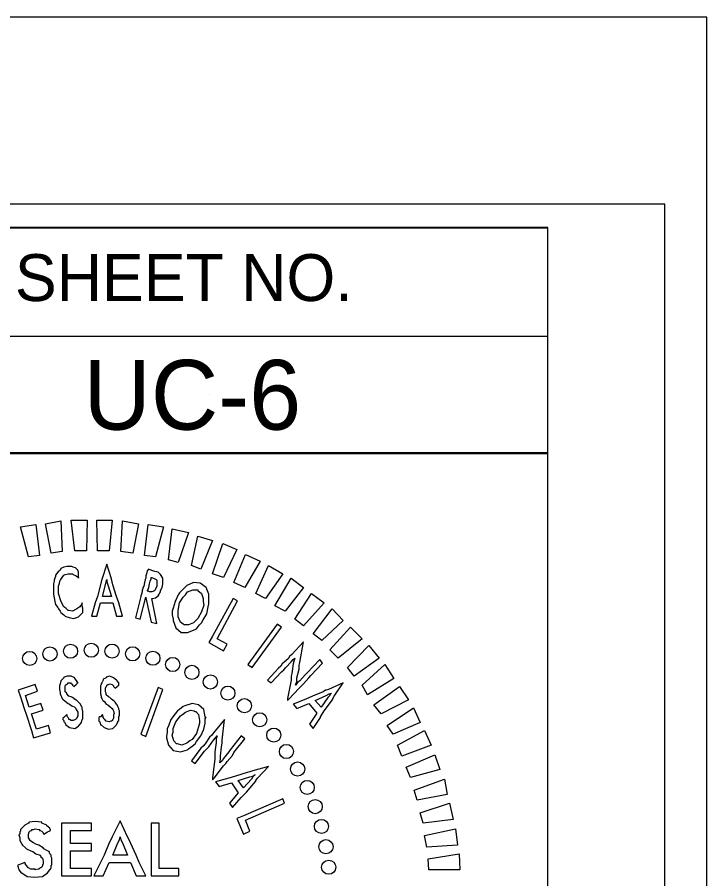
# Model space of a CAD drawing. Extents: x 0 to 7954, y -383 to 1504.
# Drawn here: x 2.7104 to 2.8333, y 1.6798 to 1.8333 of the extents above; entities that cross this region are included whole.
import ezdxf

# ---------------------------------------------------------------- set-up
doc = ezdxf.new("R2010")
doc.units = 0
for name, color, linetype in [('Concrete Pattern CELL', 7, 'Continuous'), ('UC Plan Profile Sheet 34 CELL', 7, 'Continuous'), ('UC Plan Sheet 34 CELL', 7, 'Continuous')]:
    doc.layers.add(name, color=color, linetype=linetype)

msp = doc.modelspace()

# ---------------------------------------------------------------- linework, layer by layer
at = {"layer": 'Concrete Pattern CELL'}
for points in [[(2.71245, 1.73716), (2.71101, 1.74252), (2.71376, 1.74291), (2.71441, 1.73742)], [(2.7165, 1.73781), (2.71545, 1.74304), (2.7182, 1.74357), (2.71846, 1.73808)], [(2.72068, 1.73821), (2.72003, 1.7437), (2.7229, 1.7437), (2.72277, 1.73821)], [(2.72473, 1.73821), (2.7246, 1.7437), (2.72735, 1.7437), (2.72683, 1.73821)], [(2.72892, 1.73808), (2.72918, 1.74357), (2.73205, 1.74304), (2.73101, 1.73781)], [(2.7331, 1.73742), (2.73375, 1.74291), (2.7365, 1.74252), (2.73506, 1.73716)], [(2.73741, 1.73664), (2.73807, 1.74213), (2.74094, 1.74147), (2.73911, 1.73612)], [(2.74147, 1.73559), (2.74264, 1.74082), (2.74526, 1.74004), (2.74317, 1.73494)], [(2.74526, 1.73415), (2.74709, 1.73951), (2.74957, 1.73847), (2.74722, 1.7335)], [(2.74905, 1.73259), (2.75114, 1.73755), (2.75375, 1.73638), (2.75101, 1.73167)], [(2.75297, 1.73063), (2.75519, 1.73559), (2.7578, 1.73415), (2.75467, 1.72971)], [(2.75637, 1.7284), (2.75924, 1.73337), (2.76146, 1.73167), (2.7582, 1.72749)], [(2.7599, 1.72605), (2.7629, 1.73063), (2.76512, 1.72893), (2.76146, 1.72487)], [(2.76316, 1.72344), (2.76656, 1.72788), (2.76852, 1.72579), (2.76473, 1.72226)], [(2.75676, 1.72514), (2.75153, 1.71795), (2.75231, 1.71742), (2.75754, 1.72461)], [(2.76617, 1.72056), (2.76983, 1.72461), (2.77192, 1.72252), (2.76761, 1.71912)], [(2.76931, 1.71742), (2.7731, 1.72135), (2.77493, 1.71912), (2.77048, 1.71586)], [(2.77192, 1.71429), (2.77597, 1.71795), (2.77754, 1.71546), (2.77284, 1.71259)], [(2.73558, 1.71389), (2.73245, 1.70553), (2.73336, 1.70514), (2.73637, 1.7135)], [(2.77401, 1.71076), (2.77859, 1.71403), (2.78016, 1.71167), (2.77532, 1.70919)], [(2.77637, 1.7071), (2.78107, 1.71023), (2.78225, 1.70762), (2.77741, 1.70553)], [(2.7782, 1.70357), (2.78303, 1.70618), (2.78421, 1.70357), (2.77898, 1.70161)], [(2.77976, 1.69965), (2.78486, 1.70187), (2.78578, 1.69926), (2.78055, 1.69782)], [(2.7812, 1.6956), (2.78656, 1.69756), (2.78708, 1.69481), (2.78172, 1.69377)], [(2.78225, 1.69154), (2.78748, 1.69324), (2.78813, 1.69037), (2.78277, 1.68971)], [(2.78303, 1.68749), (2.78852, 1.68867), (2.78891, 1.68579), (2.78342, 1.6854)], [(2.78369, 1.68331), (2.78918, 1.68422), (2.78931, 1.68135), (2.78382, 1.68135)]]:
    msp.add_lwpolyline(points, close=True, dxfattribs=at)
for points in [[(2.72134, 1.73442), (2.72121, 1.73481), (2.72081, 1.7352), (2.72042, 1.73533), (2.72016, 1.73546), (2.71925, 1.73546), (2.71872, 1.73533), (2.7182, 1.73507), (2.71807, 1.73481), (2.71768, 1.73442), (2.71728, 1.73389), (2.71728, 1.73376), (2.71728, 1.73363), (2.71715, 1.73337), (2.71702, 1.73298), (2.71702, 1.73285), (2.71689, 1.73232), (2.71689, 1.7318), (2.71689, 1.73049), (2.71715, 1.72919), (2.71728, 1.72866), (2.71768, 1.72814), (2.71781, 1.72788), (2.71807, 1.72749), (2.7182, 1.72723), (2.71872, 1.72683), (2.71898, 1.72657), (2.71925, 1.72644), (2.7199, 1.72631), (2.72055, 1.72618), (2.72134, 1.72644), (2.7216, 1.7267), (2.72186, 1.72697), (2.72212, 1.72723), (2.72212, 1.72775), (2.72212, 1.72801), (2.72199, 1.7284), (2.72199, 1.72866), (2.72199, 1.72893), (2.72186, 1.72866), (2.7216, 1.72827), (2.72108, 1.72788), (2.72029, 1.72749), (2.71964, 1.72762), (2.71951, 1.72762), (2.71911, 1.72801), (2.71872, 1.72827), (2.71846, 1.7288), (2.7182, 1.72932), (2.71781, 1.73063), (2.71781, 1.73193), (2.71794, 1.73246), (2.71807, 1.73298), (2.7182, 1.73311), (2.71846, 1.7335), (2.71872, 1.73389), (2.71898, 1.73402), (2.71951, 1.73415), (2.72029, 1.73415), (2.72042, 1.73402), (2.72094, 1.73376), (2.72134, 1.7335), (2.72134, 1.73337), (2.72134, 1.7335), (2.72134, 1.73389), (2.72134, 1.73415), (2.72134, 1.73429), (2.72134, 1.73442), (2.72134, 1.73442)], [(2.72722, 1.73311), (2.72722, 1.73324), (2.72643, 1.73585), (2.72552, 1.73311), (2.72539, 1.73272), (2.72526, 1.73219), (2.72473, 1.7301), (2.72434, 1.72893), (2.72369, 1.72657), (2.7246, 1.72657), (2.72526, 1.72893), (2.72748, 1.72893), (2.72813, 1.72657), (2.72918, 1.72657), (2.72853, 1.72893), (2.72813, 1.7301), (2.72748, 1.73219), (2.72735, 1.73272), (2.72722, 1.73311), (2.72722, 1.73311)], [(2.73637, 1.73298), (2.73637, 1.73337), (2.73598, 1.73402), (2.73558, 1.73442), (2.73493, 1.73455), (2.73375, 1.73494), (2.73375, 1.73481), (2.73362, 1.73468), (2.73349, 1.73415), (2.73336, 1.73376), (2.73336, 1.73363), (2.73336, 1.7335), (2.73336, 1.73337), (2.73323, 1.73311), (2.7331, 1.73259), (2.73297, 1.73193), (2.73284, 1.73167), (2.73284, 1.73141), (2.73271, 1.73128), (2.73271, 1.73089), (2.73258, 1.73049), (2.73245, 1.73023), (2.73245, 1.7301), (2.73153, 1.72631), (2.73232, 1.72605), (2.73336, 1.72997), (2.73336, 1.72984), (2.73428, 1.72553), (2.73532, 1.72527), (2.73441, 1.72971), (2.73454, 1.72971), (2.73506, 1.72984), (2.73558, 1.73023), (2.73571, 1.73049), (2.73585, 1.73076), (2.73598, 1.73089), (2.73598, 1.73115), (2.73624, 1.73167), (2.73637, 1.73232), (2.73637, 1.73259), (2.73637, 1.73272), (2.73637, 1.73298)], [(2.72643, 1.73311), (2.72643, 1.73272), (2.72656, 1.73219), (2.72722, 1.7301), (2.72565, 1.7301), (2.72617, 1.73219), (2.7263, 1.73272), (2.72643, 1.73311), (2.72643, 1.73311)], [(2.73441, 1.7335), (2.73493, 1.73324), (2.73519, 1.73311), (2.73532, 1.73298), (2.73532, 1.73259), (2.73532, 1.73193), (2.73506, 1.73141), (2.73493, 1.73115), (2.7348, 1.73102), (2.73441, 1.73089), (2.73402, 1.73089), (2.73375, 1.73102), (2.73362, 1.73102), (2.73375, 1.73128), (2.73375, 1.73141), (2.73388, 1.73167), (2.73402, 1.73232), (2.73415, 1.73285), (2.73428, 1.73324), (2.73428, 1.73337), (2.73428, 1.7335), (2.73441, 1.7335), (2.73441, 1.7335)], [(2.74186, 1.73259), (2.74068, 1.73206), (2.74055, 1.73193), (2.74042, 1.7318), (2.7399, 1.73128), (2.73937, 1.73076), (2.73911, 1.73036), (2.73859, 1.72919), (2.7382, 1.72801), (2.73807, 1.72749), (2.73807, 1.72683), (2.7382, 1.72605), (2.7382, 1.72579), (2.73872, 1.72448), (2.73964, 1.7237), (2.74081, 1.7237), (2.74212, 1.72422), (2.74238, 1.72435), (2.7429, 1.72501), (2.7433, 1.7254), (2.74356, 1.72592), (2.74421, 1.72697), (2.74447, 1.72827), (2.7446, 1.7288), (2.7446, 1.72932), (2.7446, 1.7301), (2.7446, 1.73036), (2.7446, 1.73049), (2.74408, 1.73167), (2.74303, 1.73246), (2.74186, 1.73259), (2.74186, 1.73259)], [(2.74264, 1.73128), (2.74264, 1.73115), (2.7433, 1.73063), (2.74356, 1.72971), (2.74356, 1.72919), (2.74369, 1.72853), (2.7433, 1.72736), (2.74264, 1.72618), (2.74225, 1.72579), (2.74186, 1.7254), (2.74094, 1.72501), (2.74029, 1.72501), (2.74016, 1.72501), (2.74003, 1.72514), (2.73951, 1.72553), (2.73911, 1.72644), (2.73911, 1.7271), (2.73911, 1.72762), (2.73937, 1.72893), (2.74003, 1.72997), (2.74042, 1.73036), (2.74081, 1.73089), (2.74173, 1.73128), (2.74251, 1.73128), (2.74264, 1.73128), (2.74264, 1.73128)], [(2.74526, 1.72304), (2.7446, 1.72187), (2.74722, 1.72043), (2.74787, 1.72161), (2.74604, 1.72252), (2.7497, 1.72932), (2.74892, 1.72971), (2.74526, 1.72304), (2.74526, 1.72304)], [(2.76003, 1.71429), (2.76029, 1.71494), (2.76029, 1.71559), (2.76068, 1.71716), (2.76068, 1.71782), (2.76081, 1.71834), (2.76146, 1.722), (2.75937, 1.71978), (2.75898, 1.71938), (2.75872, 1.71899), (2.75767, 1.71808), (2.75741, 1.71769), (2.75702, 1.71729), (2.75506, 1.7152), (2.75571, 1.71468), (2.75754, 1.71664), (2.75794, 1.71703), (2.75833, 1.71742), (2.75924, 1.71847), (2.75963, 1.71886), (2.7599, 1.71912), (2.75977, 1.71873), (2.75963, 1.71808), (2.75937, 1.71638), (2.75924, 1.71586), (2.75924, 1.7152), (2.75859, 1.71193), (2.75859, 1.71154), (2.75885, 1.7118), (2.76068, 1.71376), (2.76107, 1.71416), (2.76146, 1.71455), (2.76238, 1.71559), (2.76277, 1.71599), (2.76486, 1.71821), (2.76434, 1.71886), (2.76212, 1.71651), (2.76173, 1.71612), (2.76081, 1.71507), (2.76042, 1.71481), (2.76003, 1.71429), (2.76003, 1.71429)], [(2.71872, 1.71559), (2.71833, 1.7152), (2.7182, 1.71507), (2.71807, 1.71455), (2.71807, 1.71442), (2.71794, 1.71429), (2.71794, 1.71416), (2.71794, 1.71403), (2.71794, 1.71389), (2.71794, 1.71363), (2.71794, 1.7135), (2.71807, 1.71298), (2.71807, 1.71272), (2.7182, 1.71246), (2.71833, 1.7122), (2.71846, 1.71193), (2.71859, 1.7118), (2.71898, 1.71141), (2.71951, 1.71102), (2.71977, 1.71089), (2.72016, 1.71063), (2.72068, 1.71037), (2.72081, 1.71023), (2.72094, 1.70997), (2.72121, 1.70945), (2.72121, 1.70932), (2.72121, 1.70893), (2.72121, 1.7088), (2.72108, 1.70854), (2.72108, 1.7084), (2.72094, 1.70827), (2.72081, 1.70814), (2.72042, 1.70801), (2.72003, 1.70801), (2.71977, 1.70814), (2.71964, 1.70814), (2.71964, 1.70827), (2.71951, 1.70854), (2.71938, 1.70867), (2.71925, 1.70906), (2.71885, 1.70867), (2.71872, 1.70854), (2.71859, 1.7084), (2.71859, 1.70814), (2.71872, 1.70801), (2.71872, 1.70788), (2.71872, 1.70775), (2.71885, 1.70775), (2.71911, 1.70723), (2.71977, 1.70671), (2.72068, 1.70657), (2.72134, 1.70697), (2.72186, 1.70762), (2.72199, 1.70814), (2.72212, 1.70827), (2.72212, 1.70854), (2.72212, 1.70867), (2.72212, 1.70893), (2.72212, 1.70906), (2.72212, 1.70945), (2.72212, 1.70958), (2.72199, 1.7101), (2.72199, 1.71037), (2.72186, 1.7105), (2.72173, 1.71089), (2.72147, 1.71115), (2.72134, 1.71128), (2.72094, 1.71167), (2.72081, 1.71167), (2.72029, 1.71206), (2.72003, 1.7122), (2.71964, 1.71233), (2.71925, 1.71272), (2.71925, 1.71285), (2.71898, 1.71311), (2.71898, 1.71363), (2.71898, 1.71376), (2.71898, 1.71416), (2.71911, 1.71442), (2.71925, 1.71442), (2.71938, 1.71455), (2.71951, 1.71468), (2.7199, 1.71468), (2.72003, 1.71455), (2.72016, 1.71455), (2.72029, 1.71442), (2.72029, 1.71429), (2.72055, 1.71403), (2.72094, 1.71442), (2.72108, 1.71455), (2.72121, 1.71468), (2.72121, 1.71481), (2.72108, 1.71481), (2.72108, 1.71494), (2.72108, 1.71507), (2.72068, 1.71546), (2.72068, 1.71559), (2.72003, 1.71586), (2.71938, 1.71586), (2.71872, 1.71572), (2.71872, 1.71559), (2.71872, 1.71559)], [(2.7263, 1.71559), (2.72578, 1.71533), (2.72578, 1.7152), (2.72552, 1.71468), (2.72539, 1.71455), (2.72539, 1.71442), (2.72526, 1.71416), (2.72526, 1.71376), (2.72526, 1.71363), (2.72526, 1.71311), (2.72526, 1.71285), (2.72526, 1.71272), (2.72539, 1.71233), (2.72539, 1.71206), (2.72552, 1.71193), (2.72578, 1.71141), (2.72591, 1.71141), (2.7263, 1.71089), (2.72656, 1.71076), (2.72696, 1.7105), (2.72735, 1.7101), (2.72748, 1.70997), (2.72761, 1.70971), (2.72774, 1.70919), (2.72761, 1.70906), (2.72761, 1.70867), (2.72761, 1.70854), (2.72761, 1.7084), (2.72748, 1.70814), (2.72735, 1.70801), (2.72722, 1.70788), (2.72709, 1.70788), (2.72683, 1.70775), (2.7263, 1.70788), (2.72604, 1.70814), (2.72591, 1.70827), (2.72578, 1.70854), (2.72578, 1.70867), (2.72565, 1.70906), (2.72526, 1.70867), (2.72513, 1.70867), (2.725, 1.70854), (2.725, 1.70827), (2.725, 1.70814), (2.725, 1.70788), (2.72513, 1.70775), (2.72526, 1.70723), (2.72539, 1.70723), (2.72591, 1.70671), (2.7267, 1.70644), (2.72748, 1.70657), (2.72813, 1.70723), (2.72839, 1.70775), (2.72839, 1.70788), (2.72853, 1.70801), (2.72853, 1.70814), (2.72853, 1.7084), (2.72853, 1.70854), (2.72853, 1.70867), (2.72866, 1.70893), (2.72866, 1.70919), (2.72866, 1.70971), (2.72853, 1.70997), (2.72853, 1.7101), (2.72839, 1.7105), (2.72826, 1.71076), (2.72813, 1.71089), (2.72787, 1.71128), (2.72774, 1.71141), (2.72722, 1.7118), (2.72696, 1.71206), (2.7267, 1.7122), (2.7263, 1.71259), (2.7263, 1.71285), (2.72617, 1.71311), (2.72617, 1.71363), (2.72617, 1.71376), (2.7263, 1.71403), (2.72643, 1.71416), (2.72643, 1.71429), (2.72656, 1.71442), (2.7267, 1.71442), (2.72696, 1.71455), (2.72735, 1.71442), (2.72748, 1.71429), (2.72761, 1.71416), (2.72761, 1.71403), (2.72787, 1.71376), (2.72826, 1.71403), (2.72839, 1.71416), (2.72853, 1.71429), (2.72853, 1.71442), (2.72853, 1.71455), (2.72853, 1.71468), (2.72826, 1.71507), (2.72813, 1.7152), (2.72761, 1.71559), (2.72696, 1.71586), (2.7263, 1.71572), (2.7263, 1.71559), (2.7263, 1.71559)], [(2.71297, 1.70618), (2.71336, 1.70488), (2.71637, 1.70579), (2.71598, 1.7071), (2.71389, 1.70644), (2.71297, 1.70919), (2.71506, 1.70984), (2.71467, 1.71102), (2.71258, 1.71037), (2.71193, 1.71246), (2.71402, 1.71324), (2.71362, 1.71442), (2.71062, 1.71337), (2.71101, 1.7122), (2.71166, 1.7101), (2.71206, 1.70893), (2.71297, 1.70618), (2.71297, 1.70618)], [(2.76695, 1.71233), (2.76852, 1.71468), (2.76591, 1.7135), (2.76552, 1.71337), (2.76539, 1.71337), (2.76499, 1.71311), (2.76303, 1.71233), (2.76186, 1.7118), (2.75963, 1.71089), (2.76029, 1.7101), (2.76238, 1.71102), (2.76382, 1.70932), (2.76251, 1.70736), (2.76316, 1.70657), (2.76447, 1.70854), (2.76447, 1.70867), (2.76512, 1.70971), (2.76643, 1.71141), (2.76669, 1.7118), (2.76669, 1.71193), (2.76695, 1.71233), (2.76695, 1.71233)], [(2.76643, 1.71285), (2.76617, 1.71259), (2.76617, 1.71246), (2.76578, 1.71206), (2.7646, 1.71037), (2.76356, 1.71154), (2.76552, 1.71246), (2.76604, 1.71272), (2.76643, 1.71285), (2.76643, 1.71285)], [(2.7416, 1.71102), (2.74029, 1.71063), (2.74003, 1.7105), (2.73937, 1.70997), (2.73898, 1.70971), (2.73859, 1.70919), (2.73781, 1.70814), (2.73741, 1.70697), (2.73715, 1.70657), (2.73715, 1.70592), (2.73702, 1.70514), (2.73702, 1.70488), (2.73741, 1.70357), (2.7382, 1.70265), (2.73951, 1.70239), (2.74081, 1.70278), (2.74094, 1.70291), (2.7416, 1.70344), (2.74212, 1.70383), (2.74238, 1.70422), (2.74317, 1.70527), (2.74369, 1.70644), (2.74382, 1.70697), (2.74395, 1.70749), (2.74395, 1.70827), (2.74408, 1.70854), (2.74395, 1.70854), (2.74395, 1.70867), (2.74369, 1.70997), (2.74277, 1.71076), (2.7416, 1.71102), (2.7416, 1.71102)], [(2.74212, 1.70958), (2.74225, 1.70958), (2.74277, 1.70906), (2.7429, 1.70801), (2.7429, 1.70749), (2.74277, 1.70684), (2.74238, 1.70566), (2.7416, 1.70461), (2.7412, 1.70435), (2.74068, 1.70396), (2.73977, 1.70357), (2.73898, 1.70383), (2.73885, 1.70383), (2.73833, 1.70435), (2.73807, 1.7054), (2.7382, 1.70592), (2.7382, 1.70657), (2.73872, 1.70775), (2.73951, 1.7088), (2.7399, 1.70906), (2.74042, 1.70945), (2.74134, 1.70984), (2.74199, 1.70971), (2.74212, 1.70958), (2.74212, 1.70958)], [(2.74656, 1.70043), (2.74669, 1.70109), (2.74669, 1.70161), (2.74683, 1.70331), (2.74696, 1.70396), (2.74696, 1.70448), (2.74735, 1.70814), (2.74539, 1.70579), (2.74513, 1.7054), (2.74473, 1.70501), (2.74395, 1.70383), (2.74356, 1.70344), (2.74317, 1.70305), (2.74147, 1.70082), (2.74212, 1.7003), (2.74382, 1.70252), (2.74421, 1.70291), (2.7446, 1.70331), (2.74539, 1.70448), (2.74578, 1.70488), (2.74604, 1.70527), (2.74591, 1.70474), (2.74591, 1.70409), (2.74565, 1.70239), (2.74565, 1.70187), (2.74565, 1.70109), (2.74526, 1.69782), (2.74526, 1.69743), (2.74552, 1.69769), (2.74722, 1.69991), (2.74761, 1.7003), (2.74787, 1.70069), (2.74879, 1.70174), (2.74905, 1.70226), (2.75101, 1.70474), (2.75035, 1.70527), (2.74839, 1.70278), (2.74813, 1.70239), (2.74722, 1.70122), (2.74696, 1.70082), (2.74656, 1.70043), (2.74656, 1.70043)], [(2.75323, 1.69769), (2.75519, 1.69978), (2.75245, 1.69899), (2.75192, 1.69886), (2.7514, 1.69873), (2.74931, 1.69808), (2.74813, 1.69769), (2.74578, 1.69703), (2.74643, 1.69625), (2.74865, 1.6969), (2.74983, 1.69507), (2.74826, 1.69324), (2.74879, 1.69246), (2.75035, 1.69429), (2.75127, 1.6952), (2.75258, 1.69677), (2.75297, 1.69716), (2.75297, 1.69729), (2.75323, 1.69769), (2.75323, 1.69769)], [(2.75284, 1.69834), (2.75245, 1.69795), (2.75218, 1.69756), (2.75075, 1.69599), (2.74983, 1.69729), (2.75192, 1.69795), (2.75245, 1.69808), (2.75284, 1.69834), (2.75284, 1.69834)], [(2.75075, 1.69102), (2.74957, 1.6905), (2.75075, 1.68775), (2.75192, 1.68828), (2.75114, 1.69024), (2.75807, 1.69324), (2.7578, 1.69403), (2.75075, 1.69102), (2.75075, 1.69102)], [(2.71245, 1.68971), (2.71179, 1.68932), (2.71166, 1.68919), (2.71127, 1.6888), (2.71114, 1.68867), (2.71101, 1.68854), (2.71101, 1.68841), (2.71101, 1.68828), (2.71088, 1.68814), (2.71088, 1.68775), (2.71075, 1.68762), (2.71088, 1.6871), (2.71088, 1.68671), (2.71088, 1.68658), (2.71114, 1.68618), (2.71127, 1.68592), (2.7114, 1.68579), (2.71193, 1.68527), (2.71206, 1.68514), (2.71284, 1.68475), (2.71323, 1.68462), (2.71376, 1.68422), (2.71454, 1.68396), (2.71467, 1.6837), (2.71493, 1.68344), (2.71506, 1.68292), (2.71506, 1.68279), (2.71506, 1.68239), (2.71493, 1.68226), (2.71493, 1.68213), (2.7148, 1.68187), (2.71467, 1.68174), (2.71454, 1.68174), (2.71428, 1.68148), (2.71415, 1.68148), (2.71362, 1.68135), (2.71362, 1.68148), (2.71284, 1.68148), (2.71245, 1.68174), (2.71232, 1.68174), (2.71232, 1.68187), (2.71206, 1.68213), (2.71193, 1.68226), (2.71193, 1.68239), (2.71179, 1.68265), (2.71101, 1.68239), (2.71075, 1.68226), (2.71049, 1.68213), (2.71062, 1.68187), (2.71062, 1.68174), (2.71075, 1.68148), (2.71075, 1.68135), (2.71114, 1.68082), (2.71127, 1.68082), (2.71219, 1.68017), (2.71349, 1.68004), (2.71493, 1.68017), (2.71585, 1.68082), (2.71624, 1.68135), (2.71624, 1.68148), (2.71637, 1.68148), (2.7165, 1.68174), (2.7165, 1.68187), (2.7165, 1.68213), (2.71663, 1.68226), (2.71663, 1.68239), (2.71663, 1.68279), (2.71663, 1.68292), (2.71663, 1.68344), (2.7165, 1.6837), (2.7165, 1.68396), (2.71624, 1.68422), (2.71611, 1.68462), (2.71585, 1.68475), (2.71519, 1.68514), (2.71506, 1.68527), (2.71428, 1.68579), (2.71376, 1.68592), (2.71336, 1.68618), (2.71271, 1.68658), (2.71271, 1.68671), (2.71245, 1.6871), (2.71245, 1.68762), (2.71245, 1.68775), (2.71258, 1.68814), (2.71271, 1.68828), (2.71297, 1.68841), (2.7131, 1.68854), (2.71336, 1.68854), (2.71362, 1.68867), (2.71428, 1.68854), (2.71441, 1.68854), (2.71441, 1.68841), (2.71454, 1.68841), (2.7148, 1.68828), (2.71493, 1.68814), (2.71519, 1.68775), (2.71585, 1.68814), (2.71611, 1.68828), (2.71637, 1.68841), (2.71637, 1.68854), (2.71624, 1.68867), (2.71624, 1.6888), (2.71572, 1.68919), (2.71572, 1.68932), (2.7148, 1.68971), (2.7148, 1.68984), (2.71362, 1.68997), (2.71258, 1.68984), (2.71245, 1.68971), (2.71245, 1.68971)], [(2.71833, 1.68161), (2.71833, 1.6803), (2.72369, 1.6803), (2.72369, 1.68161), (2.7199, 1.68161), (2.7199, 1.68475), (2.72369, 1.68475), (2.72369, 1.68605), (2.7199, 1.68605), (2.7199, 1.68841), (2.72369, 1.68841), (2.72369, 1.68971), (2.71833, 1.68971), (2.71833, 1.68841), (2.71833, 1.68605), (2.71833, 1.68475), (2.71833, 1.68161), (2.71833, 1.68161)], [(2.73009, 1.68723), (2.72879, 1.69011), (2.72735, 1.68723), (2.72709, 1.68671), (2.72683, 1.68618), (2.72591, 1.68396), (2.72526, 1.68265), (2.72408, 1.6803), (2.72578, 1.6803), (2.72683, 1.68265), (2.73062, 1.68265), (2.73166, 1.6803), (2.73336, 1.6803), (2.73219, 1.68265), (2.73166, 1.68396), (2.73062, 1.68618), (2.73036, 1.68671), (2.73009, 1.68723), (2.73009, 1.68723)], [(2.73428, 1.68161), (2.73428, 1.6803), (2.73924, 1.6803), (2.73924, 1.68161), (2.73571, 1.68161), (2.73571, 1.68971), (2.73428, 1.68971), (2.73428, 1.68161), (2.73428, 1.68161)], [(2.72879, 1.68723), (2.72892, 1.68671), (2.72918, 1.68618), (2.73009, 1.68396), (2.72748, 1.68396), (2.72839, 1.68618), (2.72866, 1.68671), (2.72879, 1.68723), (2.72879, 1.68723)]]:
    msp.add_lwpolyline(points, dxfattribs=at)
for centre in [(2.71994, 1.72034), (2.72364, 1.72051), (2.72733, 1.72035), (2.71266, 1.71905), (2.71627, 1.71985), (2.731, 1.71987), (2.73462, 1.71908), (2.73815, 1.71797), (2.74157, 1.71656), (2.74486, 1.71485), (2.74798, 1.71287), (2.75092, 1.71062), (2.75365, 1.70812), (2.75616, 1.70539), (2.75841, 1.70246), (2.76041, 1.69934), (2.76212, 1.69606), (2.76354, 1.69264), (2.76466, 1.68911), (2.76546, 1.6855), (2.76595, 1.68183)]:
    msp.add_circle(centre, 0.00126, dxfattribs=at)
at = {"layer": 'UC Plan Profile Sheet 34 CELL'}
for points in [[(0.02749, 0.00833), (2.83333, 0.00833), (2.83333, 1.83333), (0.02749, 1.83333)], [(0.04916, 0.04166), (2.82583, 0.04166), (2.82583, 1.8), (0.04916, 1.8)], [(2.80499, 1.79583), (0.30499, 1.79583), (0.30499, 0.04583), (2.80499, 0.04583)]]:
    msp.add_lwpolyline(points, close=True, dxfattribs=at)
at = {"layer": 'UC Plan Sheet 34 CELL'}
for p, q in [((2.4719, 1.77648), (2.80496, 1.77648)), ((2.74467, 1.76604), (2.74467, 1.76604))]:
    msp.add_line(p, q, dxfattribs=at)
for points in [[(2.4719, 1.79581), (2.80496, 1.79581), (2.80496, 1.75568)], [(2.80496, 1.75568), (2.4719, 1.75568), (2.4719, 1.79581)], [(2.80496, 1.56775), (2.63979, 1.56775), (2.63979, 1.7556), (2.80496, 1.7556)], [(2.80496, 1.7556), (2.80496, 1.56775)]]:
    msp.add_lwpolyline(points, dxfattribs=at)

# ---------------------------------------------------------------- texts
at = {"layer": 'UC Plan Profile Sheet 34 CELL'}
msp.add_text('UC-6', height=0.01243, dxfattribs=at).set_placement((2.72225, 1.75982))
at = {"layer": 'UC Plan Sheet 34 CELL'}
msp.add_text('SHEET NO.', height=0.008352, dxfattribs=at).set_placement((2.71002, 1.78275))

doc.saveas('drawing.dxf')
